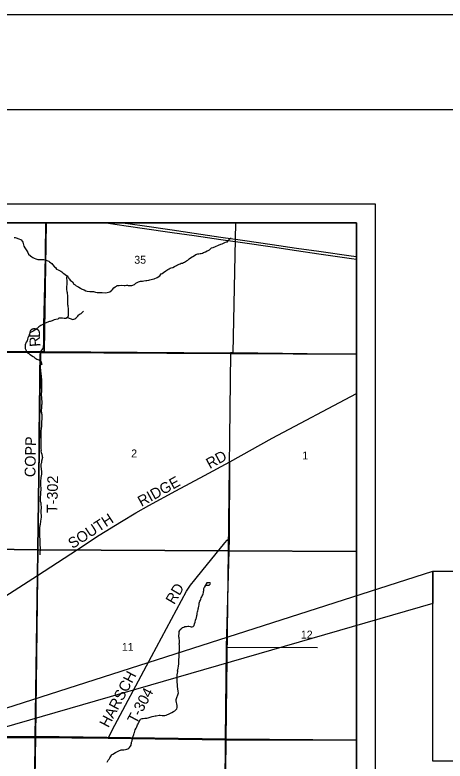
# Model space of a CAD drawing. Extents: x 0 to 34, y 0 to 22.
# Drawn here: x 7.093 to 9.369, y 18.051 to 22 of the extents above; entities that cross this region are included whole.
import ezdxf

# ---------------------------------------------------------------- set-up
doc = ezdxf.new("R2010")
doc.units = 0
for name, color, linetype in [('Default', 7, 'Continuous'), ('GM_X_County_Road', 7, 'Continuous'), ('GM_X_County_Road_Text', 7, 'Continuous'), ('GM_X_Interstate_Route', 7, 'Continuous'), ('GM_X_Minor_Lake', 7, 'Continuous'), ('GM_X_Minor_River', 7, 'Continuous'), ('GM_X_Section', 7, 'Continuous'), ('GM_X_Section_Text', 7, 'Continuous'), ('GM_X_Township_Road', 7, 'Continuous'), ('GM_X_Township_Road_Text', 7, 'Continuous'), ('SH_Border', 7, 'Continuous'), ('SH_Cut_Line', 7, 'Continuous'), ('SH_Data', 7, 'Continuous'), ('SH_Text', 7, 'Continuous')]:
    doc.layers.add(name, color=color, linetype=linetype)

msp = doc.modelspace()

# ---------------------------------------------------------------- linework, layer by layer
at = {"layer": 'Default'}
for points in [[(7.2583, 20.9), (6.2464, 20.9), (6.2399, 20.2275), (7.2272, 20.2193), (7.2465, 20.2188)], [(8.2622, 20.9), (7.2583, 20.9), (7.2465, 20.2188), (8.2331, 20.2113), (8.2479, 20.2112)], [(8.9, 19.1598), (8.9, 20.2029), (8.2479, 20.2112), (8.2331, 20.2113), (8.2209, 19.1637)], [(8.9, 18.1619), (8.9, 19.1598), (8.2209, 19.1637), (8.2084, 18.1673)], [(8.9, 17.1539), (8.9, 18.1619), (8.2084, 18.1673), (8.1974, 17.1648)]]:
    msp.add_lwpolyline(points, close=True, dxfattribs=at)
at = {"layer": 'GM_X_County_Road'}
for points in [[(7.0391, 18.9232), (7.2124, 19.0336), (7.4234, 19.1704), (7.539, 19.2472), (7.6562, 19.3185), (7.732, 19.3645), (7.8021, 19.4037), (7.9446, 19.4817), (8.0961, 19.5631), (8.2296, 19.6352), (8.4541, 19.7599), (8.9, 19.9969)], [(8.1995, 17.1669), (8.2077, 18.164), (8.2125, 18.6542), (8.228, 19.2286), (8.2296, 19.6352)]]:
    msp.add_lwpolyline(points, dxfattribs=at)
at = {"layer": 'GM_X_Interstate_Route'}
for points in [[(7.5753, 20.9), (7.6213, 20.8932), (7.7662, 20.8723), (7.9254, 20.8491), (8.0411, 20.8322), (8.183, 20.8117), (8.297, 20.795), (8.4553, 20.7722), (8.5832, 20.7537), (8.7019, 20.7365), (8.8731, 20.7119), (8.9, 20.7079)], [(7.6632, 20.9), (7.7657, 20.8852), (7.9249, 20.8621), (8.0406, 20.8451), (8.1825, 20.8247), (8.2965, 20.808), (8.4548, 20.7851), (8.5827, 20.7666), (8.7014, 20.7495), (8.8726, 20.7248), (8.9, 20.7208)]]:
    msp.add_lwpolyline(points, dxfattribs=at)
at = {"layer": 'GM_X_Minor_Lake'}
for points in [[(8.1077, 18.9939), (8.1041, 18.9902), (8.1022, 18.9864), (8.1007, 18.9819), (8.1011, 18.9819)], [(8.1011, 18.9819), (8.1071, 18.9815), (8.1208, 18.983), (8.1212, 18.9822), (8.1257, 18.9868), (8.1272, 18.9913), (8.1253, 18.994), (8.1223, 18.9947), (8.1163, 18.9955), (8.1129, 18.9955), (8.1077, 18.9939)]]:
    msp.add_lwpolyline(points, dxfattribs=at)
at = {"layer": 'GM_X_Minor_River'}
for points in [[(7.0881, 20.8226), (7.0942, 20.8215), (7.0995, 20.8204), (7.1041, 20.8193), (7.1082, 20.8167), (7.1124, 20.8144), (7.1212, 20.8118), (7.1257, 20.8099), (7.1315, 20.8031), (7.1349, 20.797), (7.1376, 20.7841), (7.14, 20.7769), (7.1442, 20.7678), (7.1491, 20.7621), (7.1518, 20.7561), (7.1556, 20.7508), (7.161, 20.7421), (7.1648, 20.7345), (7.1755, 20.7258), (7.182, 20.7198), (7.1866, 20.7171), (7.1949, 20.7126), (7.2025, 20.71), (7.2082, 20.7073), (7.2132, 20.7066), (7.2177, 20.7059), (7.2272, 20.7052), (7.2333, 20.7052), (7.2405, 20.7064), (7.2455, 20.706), (7.2538, 20.7041), (7.2618, 20.7011), (7.2713, 20.6962), (7.2755, 20.6936), (7.2831, 20.6883), (7.2877, 20.6849), (7.2919, 20.68), (7.3026, 20.6664), (7.3068, 20.6626), (7.3121, 20.6554), (7.3213, 20.6513), (7.3255, 20.649), (7.3361, 20.6445), (7.3403, 20.6411), (7.3468, 20.6354), (7.3514, 20.632), (7.3582, 20.6264), (7.3655, 20.6215), (7.37, 20.6192), (7.3731, 20.6147), (7.3754, 20.6105), (7.3784, 20.6056), (7.3819, 20.6014), (7.3846, 20.5965), (7.3964, 20.5882)], [(8.2038, 20.7957), (8.2118, 20.7984), (8.2178, 20.7996), (8.2219, 20.8061), (8.2268, 20.8115), (8.2325, 20.8161), (8.2362, 20.8211)], [(7.3964, 20.5882), (7.4041, 20.5746), (7.4113, 20.5716), (7.4167, 20.5656), (7.4247, 20.5623), (7.43, 20.5593), (7.4388, 20.5544), (7.4442, 20.5514), (7.4487, 20.5488), (7.4537, 20.547), (7.4594, 20.5444), (7.4685, 20.5403), (7.4754, 20.5381), (7.4898, 20.5367), (7.4967, 20.536), (7.5031, 20.5357), (7.508, 20.5365), (7.5187, 20.5336), (7.5278, 20.5318), (7.5388, 20.5319), (7.5464, 20.5312), (7.5536, 20.5309), (7.5719, 20.5288), (7.5802, 20.5308), (7.5878, 20.5327), (7.5957, 20.5355), (7.6047, 20.5432), (7.6085, 20.5478), (7.6164, 20.5566), (7.6228, 20.5616), (7.63, 20.5654), (7.6345, 20.5674), (7.639, 20.5682), (7.644, 20.5686), (7.6569, 20.5691), (7.6702, 20.5685), (7.6755, 20.5689), (7.6831, 20.5694), (7.6876, 20.5691), (7.6925, 20.5683), (7.7066, 20.5677), (7.7119, 20.5689), (7.7251, 20.5736), (7.7327, 20.5801), (7.7459, 20.5867), (7.7523, 20.5895), (7.7572, 20.591), (7.7682, 20.5919), (7.7754, 20.5931), (7.7849, 20.5943), (7.7906, 20.5952), (7.8016, 20.5972), (7.8072, 20.5984), (7.8213, 20.6012), (7.8288, 20.6039), (7.8462, 20.6109), (7.8586, 20.6198), (7.8624, 20.6248), (7.8673, 20.6297), (7.8722, 20.6321), (7.8786, 20.6371), (7.8907, 20.6455), (7.9016, 20.6525), (7.908, 20.656), (7.9144, 20.6591), (7.9201, 20.661), (7.928, 20.6642), (7.9367, 20.668), (7.9477, 20.6746), (7.9526, 20.6781), (7.967, 20.6824), (7.973, 20.6863), (7.9787, 20.6871), (7.9843, 20.6902), (7.9896, 20.6925), (7.9949, 20.6956), (7.9998, 20.6983), (8.007, 20.7029), (8.0153, 20.7087), (8.0224, 20.7137), (8.0421, 20.7268), (8.0504, 20.7319), (8.0553, 20.7342), (8.0606, 20.7354), (8.0666, 20.7358), (8.0738, 20.7378), (8.0784, 20.7382), (8.0852, 20.7398), (8.0905, 20.7421), (8.0965, 20.7449), (8.1011, 20.7464), (8.1094, 20.7511), (8.1154, 20.7538), (8.1218, 20.7561), (8.1275, 20.7623), (8.1331, 20.7669), (8.1414, 20.7696), (8.183, 20.7864), (8.1902, 20.7891), (8.1963, 20.7922), (8.2038, 20.7957)], [(7.368, 20.6202), (7.3666, 20.6139), (7.3663, 20.6089), (7.3663, 20.6032), (7.3671, 20.5964), (7.3668, 20.5835), (7.3664, 20.574), (7.3654, 20.5637), (7.365, 20.5596), (7.365, 20.5508), (7.3662, 20.5463), (7.367, 20.5371), (7.3686, 20.5311), (7.3693, 20.5261), (7.3705, 20.5159), (7.3706, 20.5117), (7.371, 20.5056), (7.3711, 20.4779), (7.3715, 20.468), (7.3719, 20.4623), (7.3723, 20.4574), (7.3735, 20.4456), (7.3736, 20.4327), (7.3744, 20.4251), (7.3748, 20.4183), (7.3748, 20.4133), (7.3745, 20.4069), (7.3715, 20.3985), (7.3628, 20.3935), (7.3537, 20.3943), (7.3449, 20.395), (7.3392, 20.3957), (7.3343, 20.3957), (7.3301, 20.396), (7.3252, 20.3945), (7.3188, 20.3907), (7.3082, 20.3883), (7.3002, 20.386), (7.296, 20.3845), (7.2892, 20.3803), (7.2797, 20.3776), (7.2756, 20.3775), (7.2521, 20.3687), (7.2453, 20.3656), (7.2339, 20.3587), (7.229, 20.3564), (7.2199, 20.3488), (7.2157, 20.3454), (7.2097, 20.3411), (7.204, 20.335), (7.1972, 20.3312), (7.1919, 20.3278), (7.1813, 20.3224), (7.1756, 20.3201), (7.1711, 20.3159), (7.1685, 20.3094), (7.1681, 20.3045), (7.1644, 20.2984), (7.1617, 20.2912), (7.1599, 20.2847), (7.1573, 20.2759), (7.1527, 20.2679), (7.1471, 20.255), (7.146, 20.2485), (7.1464, 20.2432), (7.1476, 20.2341), (7.1495, 20.2277), (7.1514, 20.2235), (7.1537, 20.2193), (7.1595, 20.2121), (7.1656, 20.208), (7.1698, 20.2046), (7.1739, 20.2023), (7.1804, 20.1974), (7.1892, 20.1921), (7.1934, 20.1899), (7.1987, 20.1861), (7.209, 20.1789), (7.2189, 20.1744), (7.2231, 20.1733), (7.2292, 20.1673), (7.2311, 20.1631), (7.2357, 20.1506), (7.2277, 20.1509), (7.2266, 20.1418), (7.2267, 20.1319), (7.2279, 20.1202), (7.2283, 20.1156), (7.2299, 20.1031), (7.2315, 20.0886), (7.2319, 20.0829), (7.2327, 20.0708), (7.2335, 20.0548), (7.2335, 20.0503), (7.2332, 20.0396), (7.2325, 20.0282), (7.2326, 20.0168), (7.2323, 20.0055), (7.2319, 19.9963), (7.2316, 19.9891), (7.2328, 19.9758)], [(7.3716, 20.3987), (7.3983, 20.3891), (7.4036, 20.3896), (7.4089, 20.3919), (7.4141, 20.3954), (7.4187, 20.3992), (7.4254, 20.4061), (7.4284, 20.4115), (7.4329, 20.4149), (7.4386, 20.4176), (7.4439, 20.4204), (7.4499, 20.4273), (7.4559, 20.4319)], [(7.2328, 19.9758), (7.2336, 19.9663), (7.2344, 19.9538), (7.2341, 19.9394), (7.2337, 19.9348), (7.2327, 19.9238), (7.2323, 19.9192), (7.2312, 19.9086), (7.2309, 19.901), (7.2324, 19.8968), (7.2336, 19.8904), (7.2344, 19.885), (7.2348, 19.8801), (7.2348, 19.8653), (7.2341, 19.86), (7.2338, 19.8493), (7.2338, 19.8448), (7.2331, 19.8303), (7.2332, 19.8246), (7.2313, 19.8106), (7.2302, 19.798), (7.2295, 19.7901), (7.2292, 19.7783), (7.2292, 19.7703), (7.2297, 19.76), (7.2298, 19.7399), (7.2294, 19.7308), (7.2299, 19.7179), (7.2303, 19.7042), (7.2311, 19.6959), (7.23, 19.6917), (7.232, 19.6845), (7.2354, 19.675), (7.237, 19.664), (7.2378, 19.6587), (7.2333, 19.6381), (7.2326, 19.6294), (7.2292, 19.6233), (7.2297, 19.6127), (7.2301, 19.6085), (7.2312, 19.5994), (7.2316, 19.5941), (7.2328, 19.5857), (7.2329, 19.5701), (7.2314, 19.5618), (7.2303, 19.5526), (7.2292, 19.5462), (7.2281, 19.5359), (7.2278, 19.5306), (7.2282, 19.5207), (7.2286, 19.5154), (7.2286, 19.5105), (7.2291, 19.4949), (7.2291, 19.4873), (7.2281, 19.4751), (7.2274, 19.4611), (7.2267, 19.4501), (7.2263, 19.4455), (7.2263, 19.4413), (7.226, 19.4368), (7.2264, 19.4261), (7.2291, 19.4182), (7.2303, 19.4106), (7.2303, 19.4056), (7.2307, 19.3988), (7.2308, 19.3893), (7.2289, 19.3775), (7.2294, 19.368), (7.2298, 19.3631), (7.2306, 19.3509), (7.231, 19.3468), (7.2306, 19.3422), (7.2288, 19.3312), (7.2277, 19.3217), (7.2255, 19.3042), (7.2244, 19.2977), (7.2233, 19.286), (7.2233, 19.281), (7.223, 19.2681), (7.2231, 19.2601), (7.2227, 19.2499), (7.2232, 19.2404), (7.2232, 19.2358), (7.2236, 19.2278), (7.224, 19.2218), (7.2244, 19.2134), (7.2245, 19.2066), (7.2249, 19.1918), (7.2253, 19.1826), (7.2258, 19.1697), (7.2254, 19.1644), (7.2251, 19.1599), (7.2247, 19.1549), (7.2248, 19.1481), (7.2244, 19.1428)], [(7.9454, 18.3766), (7.9576, 18.4128), (7.956, 18.4196), (7.954, 18.4363), (7.9535, 18.4439), (7.9535, 18.4485), (7.9526, 18.4583), (7.9514, 18.4674), (7.9513, 18.472), (7.9516, 18.4826), (7.9512, 18.4876), (7.9515, 18.5009), (7.9521, 18.5081), (7.9528, 18.5164), (7.9539, 18.5237), (7.9538, 18.5294), (7.9549, 18.5347), (7.956, 18.5431), (7.9574, 18.5533), (7.9596, 18.5659), (7.9599, 18.5731), (7.9606, 18.5796), (7.9609, 18.5895), (7.9611, 18.6005), (7.9611, 18.6088), (7.9618, 18.6161), (7.9621, 18.6221), (7.962, 18.629), (7.9627, 18.6351), (7.9631, 18.64), (7.9638, 18.6449), (7.9637, 18.6567), (7.9632, 18.6635), (7.9624, 18.6727), (7.9627, 18.6772), (7.9627, 18.6822), (7.963, 18.6867), (7.9629, 18.692), (7.9621, 18.6981), (7.9613, 18.703), (7.9609, 18.7095), (7.9608, 18.7159), (7.9611, 18.7247), (7.9615, 18.7292), (7.9625, 18.7365), (7.9647, 18.743), (7.9677, 18.7479), (7.9756, 18.7548), (7.9802, 18.7579), (7.9866, 18.761), (7.9915, 18.763), (7.996, 18.7634), (8.0013, 18.7642), (8.007, 18.7662), (8.0135, 18.7651), (8.0196, 18.7633), (8.0253, 18.7618), (8.0306, 18.7622), (8.0359, 18.7642), (8.0408, 18.7692), (8.0437, 18.7779), (8.0459, 18.7863), (8.0488, 18.7977), (8.0518, 18.8054), (8.0533, 18.8103), (8.0547, 18.821), (8.0562, 18.8274), (8.0572, 18.835), (8.0587, 18.8415), (8.0605, 18.8465), (8.0616, 18.8533), (8.0631, 18.8579), (8.0638, 18.8625), (8.0652, 18.8705), (8.0671, 18.8788), (8.0685, 18.8864), (8.0696, 18.8918), (8.0718, 18.8983), (8.074, 18.9032), (8.0759, 18.9082), (8.0789, 18.9147), (8.0815, 18.9204), (8.0837, 18.9253), (8.0867, 18.9314), (8.0885, 18.9368), (8.09, 18.9433), (8.0911, 18.9497), (8.0918, 18.9547), (8.0921, 18.96), (8.0928, 18.9646), (8.1005, 18.9819), (8.0954, 18.9703)], [(7.5801, 18.0459), (7.5868, 18.0555), (7.5913, 18.0616), (7.5946, 18.0685), (7.6014, 18.0788), (7.6044, 18.0849), (7.6104, 18.0887), (7.624, 18.0972), (7.6312, 18.1003), (7.6421, 18.1058), (7.6546, 18.1105), (7.6607, 18.1105), (7.669, 18.1114), (7.6785, 18.1126), (7.6857, 18.1146), (7.6906, 18.1169), (7.6955, 18.1196), (7.6996, 18.1242), (7.7049, 18.1303), (7.7079, 18.1353), (7.7082, 18.1402), (7.7097, 18.146), (7.7104, 18.1517), (7.7122, 18.1585), (7.7133, 18.1638), (7.7159, 18.1718), (7.717, 18.1772), (7.7217, 18.192), (7.724, 18.1985), (7.7254, 18.2035), (7.7273, 18.2099), (7.7295, 18.2176), (7.7347, 18.2263), (7.7377, 18.2325), (7.7403, 18.2374), (7.7414, 18.2427), (7.7447, 18.2489), (7.7492, 18.2569), (7.7529, 18.2656), (7.7563, 18.2725), (7.7665, 18.2768), (7.771, 18.2776), (7.7805, 18.2777), (7.7858, 18.2781), (7.7911, 18.2793), (7.7976, 18.2805), (7.8025, 18.2821), (7.8131, 18.2852), (7.8191, 18.2872), (7.8275, 18.2888), (7.8343, 18.2904), (7.84, 18.2916), (7.8555, 18.2936), (7.8616, 18.2941), (7.8722, 18.293), (7.8783, 18.2927), (7.8855, 18.2924), (7.8938, 18.2936), (7.8999, 18.2971), (7.9055, 18.3002), (7.9131, 18.3037), (7.9237, 18.3091), (7.932, 18.313), (7.9388, 18.3169), (7.9467, 18.3238), (7.9497, 18.3288), (7.9515, 18.3345), (7.9518, 18.3406), (7.9514, 18.3451), (7.9487, 18.3542), (7.9475, 18.361), (7.9458, 18.3705), (7.9454, 18.3766)]]:
    msp.add_lwpolyline(points, dxfattribs=at)
at = {"layer": 'GM_X_Section'}
for points in [[(6.2255, 20.2272), (6.2399, 20.2275), (7.2272, 20.2193), (7.2134, 19.1698), (6.2144, 19.1838)], [(7.2272, 20.2193), (7.2465, 20.2188), (8.2331, 20.2113), (8.2209, 19.1637), (7.2134, 19.1698)], [(6.2144, 19.1838), (7.2134, 19.1698), (7.2022, 18.181), (6.1951, 18.1802)], [(7.2134, 19.1698), (8.2209, 19.1637), (8.2084, 18.1673), (7.2022, 18.181)], [(7.2022, 18.181), (7.1859, 17.1752), (6.185, 17.1797), (6.1951, 18.1802)], [(7.2022, 18.181), (8.2084, 18.1673), (8.1974, 17.1648), (7.1859, 17.1752)]]:
    msp.add_lwpolyline(points, close=True, dxfattribs=at)
at = {"layer": 'GM_X_Township_Road'}
for p, q in [((8.2125, 18.6542), (8.6937, 18.6531)), ((5.9465, 18.1768), (7.1989, 18.1769)), ((8.2077, 18.164), (8.9, 18.1643))]:
    msp.add_line(p, q, dxfattribs=at)
msp.add_lwpolyline([(8.9, 20.2053), (8.9, 20.9), (3.2412, 20.9), (3.2371, 20.748), (3.2241, 20.2443), (4.224, 20.2365), (5.2207, 20.2288), (6.0936, 20.222), (6.4763, 20.2191), (7.2271, 20.2132)], close=True, dxfattribs=at)
for points in [[(7.237, 20.228), (7.2407, 20.2325), (7.2433, 20.2388), (7.2445, 20.2463), (7.2448, 20.2569), (7.2452, 20.2849), (7.2464, 20.3599), (7.2478, 20.4282), (7.2492, 20.4967), (7.252, 20.6446), (7.2535, 20.7236), (7.2539, 20.7565), (7.2553, 20.8745), (7.2554, 20.9)], [(8.9, 14.1483), (8.9, 20.2053), (7.2271, 20.2132), (6.4763, 20.2191), (6.0936, 20.222), (5.2207, 20.2288), (4.224, 20.2365), (3.2241, 20.2443), (3.2118, 19.2455), (3.2116, 19.2346), (3.2069, 18.535), (3.1896, 17.5787), (3.1895, 17.5705), (3.1894, 17.563), (3.1774, 16.6219), (3.1774, 16.6199), (3.1628, 15.2158), (3.1576, 14.794), (3.1491, 14.2171)], [(7.2189, 19.5327), (7.2195, 19.5762), (7.2204, 19.6894), (7.2216, 19.8091), (7.2229, 19.8837), (7.2248, 20.0896), (7.2256, 20.2046), (7.2274, 20.2127), (7.2276, 20.2137), (7.2313, 20.2206)], [(7.2313, 20.2206), (7.2318, 20.2215), (7.2352, 20.2258), (7.237, 20.228)], [(7.2124, 19.0336), (7.2136, 19.1293), (7.2147, 19.2225), (7.2165, 19.3466), (7.2177, 19.4361), (7.2187, 19.5149), (7.2189, 19.5327)], [(7.5853, 18.1728), (7.6207, 18.2415), (7.7886, 18.5558), (7.9473, 18.8514), (8.0005, 18.9507), (8.0224, 18.9821), (8.0454, 19.0101), (8.0897, 19.0655), (8.1743, 19.1692), (8.2036, 19.2063), (8.216, 19.2209), (8.2234, 19.2264), (8.228, 19.2286)], [(7.1906, 17.1758), (7.1989, 18.1769), (7.2124, 19.0336)], [(7.1989, 18.1769), (7.5853, 18.1728), (8.2077, 18.164)]]:
    msp.add_lwpolyline(points, dxfattribs=at)
at = {"layer": 'SH_Border'}
msp.add_lwpolyline([(1.5, 21.5), (33.5, 21.5), (33.5, 0.5), (1.5, 0.5)], close=True, dxfattribs=at)
at = {"layer": 'SH_Cut_Line'}
msp.add_lwpolyline([(0, 0), (34, 0), (34, 22), (0, 22)], close=True, dxfattribs=at)
msp.add_lwpolyline([(8.9, 14.1483), (8.9, 20.9), (2.1, 20.9), (2.1, 14.2219)], dxfattribs=at)
at = {"layer": 'SH_Data'}
for p, q in [((2, 21), (9, 21)), ((9, 21), (9, 14)), ((2.1, 20.9), (8.9, 20.9)), ((8.9, 20.9), (8.9, 14.1))]:
    msp.add_line(p, q, dxfattribs=at)
at = {"layer": 'SH_Text'}
for points in [[(3.8857, 17.3198), (9.3048, 19.0572), (9.3048, 18.8857)], [(9.3048, 19.0572), (12.596, 19.0572), (12.596, 18.0516), (9.3048, 18.0516)]]:
    msp.add_lwpolyline(points, close=True, dxfattribs=at)

# ---------------------------------------------------------------- texts
at = {"layer": 'GM_X_County_Road_Text'}
for s, rotation, p in [('RD', 28.7672, (8.1238, 19.5962)), ('RIDGE', 28.8864, (7.7621, 19.3962)), ('SOUTH', 33.1196, (7.3974, 19.1728))]:
    msp.add_text(s, height=0.05682, rotation=rotation, dxfattribs=at).set_placement(p)
at = {"layer": 'GM_X_Section_Text'}
for s, height, p in [('35', 0.04186, (7.7242, 20.6833)), ('2', 0.0419, (7.7079, 19.6586)), ('1', 0.0419, (8.6133, 19.6475)), ('12', 0.04186, (8.6058, 18.6999)), ('11', 0.04186, (7.6587, 18.635))]:
    msp.add_text(s, height=height, rotation=0, dxfattribs=at).set_placement(p)
at = {"layer": 'GM_X_Township_Road_Text'}
for s, height, rotation, p in [('D', 0.0568, 89.0783, (7.2249, 20.2911)), ('R', 0.0568, 94.3677, (7.2285, 20.246)), ('COPP', 0.05682, 88.8978, (7.2006, 19.5537)), ('T-302', 0.05682, 88.8762, (7.3173, 19.363)), ('RD', 0.05682, 59.4603, (7.9353, 18.8763)), ('HARSCH', 0.05682, 62, (7.5869, 18.2246)), ('T-304', 0.05682, 61.9274, (7.7341, 18.2444))]:
    msp.add_text(s, height=height, rotation=rotation, dxfattribs=at).set_placement(p)

doc.saveas('drawing.dxf')
